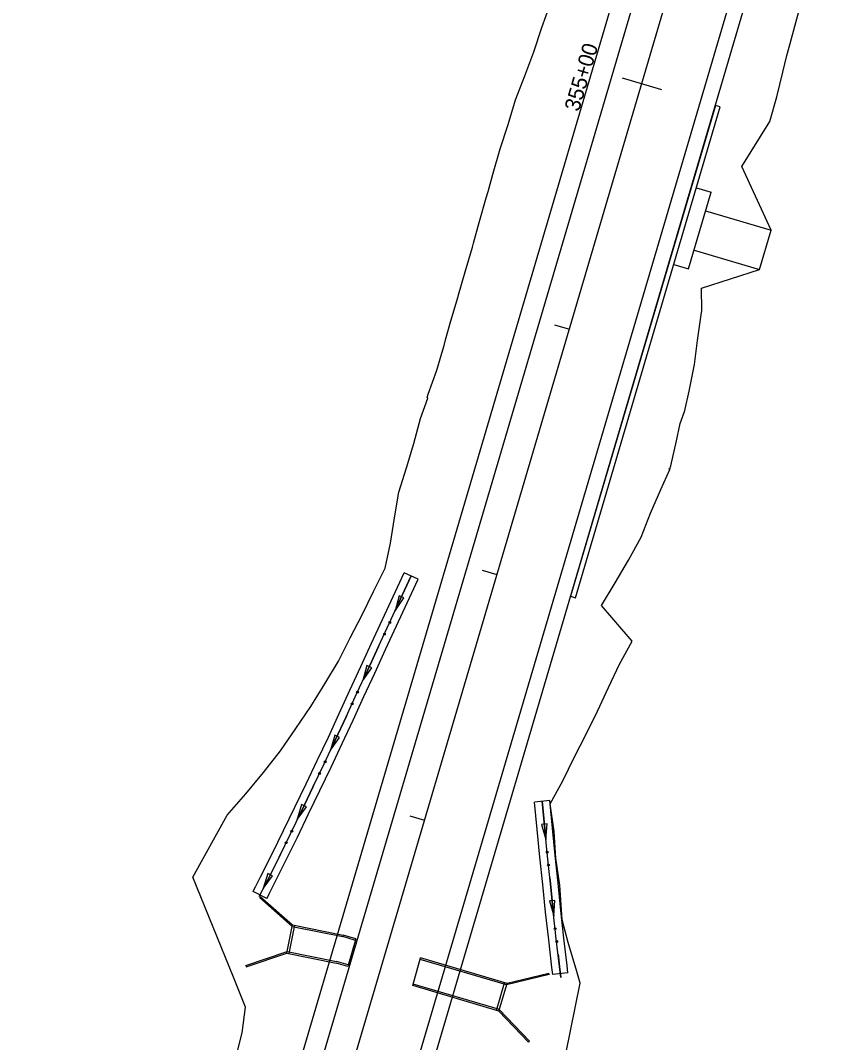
# Model space of a CAD drawing. Extents: x 948761 to 996004, y 1858548 to 1925175.
# Drawn here: x 961025.4 to 961348.3, y 1906157.3 to 1906556.8 of the extents above; entities that cross this region are included whole.
import ezdxf

# ---------------------------------------------------------------- set-up
doc = ezdxf.new("R2010")
doc.units = 0
for name, color, linetype in [('62', 7, 'Continuous'), ('R_Drainage', 7, 'Continuous'), ('R_Horz Alg', 7, 'Continuous'), ('R_Horz Alg Annot', 7, 'Continuous'), ('R_Proposed Const Limits', 7, 'Continuous'), ('R_Proposed Road', 7, 'Continuous')]:
    doc.layers.add(name, color=color, linetype=linetype)

msp = doc.modelspace()

# ---------------------------------------------------------------- linework, layer by layer
at = {"layer": '62'}
for p, q in [((961180.83, 1906338.42), (961175.38, 1906340.94)), ((961173.37, 1906331.95), (961171.81, 1906326.06)), ((961171.81, 1906326.06), (961175.29, 1906331.06)), ((961175.29, 1906331.06), (961173.37, 1906331.95)), ((961160.77, 1906304.68), (961159.22, 1906298.79)), ((961159.22, 1906298.79), (961162.69, 1906303.8)), ((961162.69, 1906303.8), (961160.77, 1906304.68)), ((961148.22, 1906277.4), (961146.61, 1906271.53)), ((961150.14, 1906276.49), (961148.22, 1906277.4)), ((961146.61, 1906271.53), (961150.14, 1906276.49)), ((961135.26, 1906250.31), (961133.61, 1906244.45)), ((961133.61, 1906244.45), (961137.16, 1906249.4)), ((961137.16, 1906249.4), (961135.26, 1906250.31)), ((961232.3, 1906251.88), (961226.33, 1906251.3)), ((961231.23, 1906242.74), (961229.13, 1906242.52)), ((961229.13, 1906242.52), (961230.79, 1906236.66)), ((961230.79, 1906236.66), (961231.23, 1906242.74)), ((961122.05, 1906223.35), (961120.31, 1906217.51)), ((961120.31, 1906217.51), (961123.94, 1906222.41)), ((961123.94, 1906222.41), (961122.05, 1906223.35)), ((961121.71, 1906213.61), (961116.34, 1906216.29)), ((961234.3, 1906212.86), (961232.2, 1906212.64)), ((961232.2, 1906212.64), (961233.86, 1906206.78)), ((961233.86, 1906206.78), (961234.3, 1906212.86)), ((961239.42, 1906184.56), (961233.46, 1906183.87))]:
    msp.add_line(p, q, dxfattribs=at)
for points in [[(961116.34, 1906216.29), (961117.32, 1906218.24), (961117.41, 1906218.43), (961119.23, 1906222.06), (961123.77, 1906231.13), (961128.24, 1906240.22), (961132.63, 1906249.33), (961137.03, 1906258.46), (961141.42, 1906267.59), (961145.75, 1906276.71), (961149.97, 1906285.87), (961154.19, 1906295.05), (961158.42, 1906304.23), (961162.65, 1906313.41), (961175.38, 1906340.94)], [(961118.73, 1906214.35), (961120, 1906216.89), (961120.09, 1906217.08), (961121.91, 1906220.71), (961126.46, 1906229.8), (961130.94, 1906238.9), (961135.33, 1906248.03), (961139.73, 1906257.16), (961144.12, 1906266.29), (961148.46, 1906275.44), (961152.69, 1906284.62), (961156.92, 1906293.8), (961161.15, 1906302.98), (961165.38, 1906312.15), (961169.62, 1906321.33), (961173.86, 1906330.5), (961178.1, 1906339.68)], [(961121.71, 1906213.61), (961122.68, 1906215.55), (961122.77, 1906215.74), (961124.59, 1906219.37), (961129.15, 1906228.47), (961133.63, 1906237.59), (961138.03, 1906246.73), (961142.43, 1906255.86), (961146.83, 1906265), (961151.18, 1906274.17), (961155.41, 1906283.36), (961159.64, 1906292.54), (961163.87, 1906301.72), (961168.1, 1906310.9), (961180.83, 1906338.42)], [(961178.1, 1906339.68), (961173.86, 1906330.5), (961171.81, 1906326.06)], [(961165.5, 1906312.41), (961165.38, 1906312.15), (961161.15, 1906302.98), (961159.22, 1906298.79)], [(961165.51, 1906312.45), (961165.5, 1906312.41)], [(961152.93, 1906285.13), (961152.69, 1906284.62), (961148.46, 1906275.44), (961146.61, 1906271.53)], [(961152.94, 1906285.17), (961152.93, 1906285.13)], [(961140.11, 1906257.96), (961139.73, 1906257.16), (961135.33, 1906248.03), (961133.61, 1906244.45)], [(961140.13, 1906258), (961140.11, 1906257.96)], [(961233.46, 1906183.87), (961233.13, 1906186.68), (961231.88, 1906197.49), (961230.69, 1906208.28), (961229.59, 1906219.04), (961228.48, 1906229.8), (961227.38, 1906240.55), (961226.33, 1906251.3)], [(961236.61, 1906182.71), (961236.11, 1906187.03), (961234.86, 1906197.82), (961233.67, 1906208.6), (961232.57, 1906219.35), (961231.47, 1906230.1), (961230.36, 1906240.85), (961229.32, 1906251.59)], [(961229.32, 1906251.59), (961230.36, 1906240.85), (961230.79, 1906236.66)], [(961239.42, 1906184.56), (961239.09, 1906187.37), (961237.84, 1906198.16), (961236.66, 1906208.92), (961235.56, 1906219.66), (961234.45, 1906230.41), (961233.35, 1906241.15), (961232.3, 1906251.88)], [(961127.02, 1906230.93), (961126.46, 1906229.8), (961121.91, 1906220.71), (961120.31, 1906217.51)], [(961127.03, 1906230.97), (961127.02, 1906230.93)], [(961232.33, 1906221.74), (961232.33, 1906221.7)], [(961232.33, 1906221.7), (961232.57, 1906219.35), (961233.67, 1906208.6), (961233.87, 1906206.78)], [(961235.55, 1906191.87), (961235.55, 1906191.84)], [(961235.55, 1906191.84), (961236.11, 1906187.03), (961236.61, 1906182.71)]]:
    msp.add_lwpolyline(points, dxfattribs=at)
for centre in [(961169.74, 1906321.5), (961167.64, 1906316.96), (961157.16, 1906294.23), (961155.06, 1906289.68), (961144.5, 1906266.99), (961142.33, 1906262.47), (961131.47, 1906239.92), (961129.26, 1906235.42), (961231.34, 1906231.68), (961231.85, 1906226.7), (961234.46, 1906201.81), (961235.01, 1906196.83)]:
    msp.add_circle(centre, 0.375, dxfattribs=at)
at = {"layer": 'R_Drainage'}
for p, q in [((961118.82, 1906214.03), (961131.66, 1906202.7)), ((961119.15, 1906214.41), (961131.7, 1906203.32)), ((961129.47, 1906192.3), (961131.7, 1906203.32)), ((961130.45, 1906192.1), (961132.68, 1906203.13)), ((961131.66, 1906202.7), (961151.36, 1906198.71)), ((961131.7, 1906203.32), (961151.51, 1906199.32)), ((961156.37, 1906197.24), (961151.36, 1906198.71)), ((961156.54, 1906197.84), (961151.51, 1906199.32)), ((961113.44, 1906187.44), (961129.68, 1906192.89)), ((961113.6, 1906186.96), (961129.47, 1906192.3)), ((961129.47, 1906192.3), (961148.8, 1906188.39)), ((961129.68, 1906192.89), (961148.95, 1906189)), ((961215.45, 1906179.81), (961181.62, 1906189.79)), ((961215.63, 1906180.41), (961181.79, 1906190.39)), ((961113.44, 1906187.44), (961113.6, 1906186.96)), ((961153.36, 1906187.04), (961148.8, 1906188.39)), ((961153.54, 1906187.64), (961148.95, 1906189)), ((961232.03, 1906183.85), (961215.37, 1906179.84)), ((961231.91, 1906184.34), (961215.63, 1906180.41)), ((961231.91, 1906184.34), (961232.03, 1906183.85)), ((961212.44, 1906169.62), (961178.73, 1906179.56)), ((961212.62, 1906170.22), (961178.9, 1906180.17)), ((961211.49, 1906169.9), (961214.67, 1906180.69)), ((961212.44, 1906169.62), (961215.63, 1906180.41)), ((961223.99, 1906157.48), (961212.44, 1906169.62)), ((961224.35, 1906157.83), (961212.54, 1906170.24)), ((961224.35, 1906157.83), (961223.99, 1906157.48))]:
    msp.add_line(p, q, dxfattribs=at)
for points in [[(961156.54, 1906197.84), (961153.36, 1906187.04)], [(961178.73, 1906179.56), (961181.79, 1906190.39)]]:
    msp.add_lwpolyline(points, dxfattribs=at)
at = {"layer": 'R_Horz Alg'}
msp.add_line((961044.57, 1905773.69), (961317.38, 1906698.54), dxfattribs=at)
at = {"layer": 'R_Horz Alg Annot'}
for points in [[(961260.59, 1906534.29), (961275.93, 1906529.77)], [(961234.21, 1906437.81), (961239.97, 1906436.11)], [(961205.92, 1906341.9), (961211.67, 1906340.2)], [(961177.63, 1906245.98), (961183.38, 1906244.29)]]:
    msp.add_lwpolyline(points, dxfattribs=at)
at = {"layer": 'R_Proposed Const Limits'}
for points in [[(961318.87, 1906474.81), (961307.38, 1906499.64), (961318.37, 1906517.25), (961321.02, 1906526.89), (961323.37, 1906536.62), (961325.03, 1906543.03), (961325.91, 1906546.3), (961328.5, 1906555.96), (961331.1, 1906565.62), (961331.62, 1906567.55), (961333.74, 1906575.27), (961335.67, 1906582), (961336.49, 1906584.89), (961339.24, 1906594.5), (961339.83, 1906596.41), (961342.19, 1906604.05), (961345.16, 1906613.6), (961348.32, 1906623.1)], [(961167.98, 1906342.66), (961170, 1906352.49), (961171.63, 1906362.44), (961173.34, 1906372.36), (961176.25, 1906381.93), (961179.18, 1906391.49), (961181.78, 1906401.15), (961184.65, 1906409.2), (961184.68, 1906409.26), (961184.68, 1906409.27), (961184.33, 1906409.37), (961184.83, 1906410.67), (961188.19, 1906420.11), (961190.14, 1906426.71), (961190.98, 1906429.71), (961191.58, 1906431.92), (961193.69, 1906439.34), (961196.52, 1906448.93), (961196.69, 1906449.52), (961199.2, 1906458.56), (961202.07, 1906468.14), (961202.54, 1906469.69), (961204.72, 1906477.79), (961207.46, 1906487.41), (961208.18, 1906489.92), (961210.17, 1906497.03), (961212.92, 1906506.65), (961216.02, 1906516.16), (961218.97, 1906525.72), (961222.52, 1906535.09), (961226.07, 1906544.47), (961229.16, 1906553.99), (961232.64, 1906563.39)], [(961232.44, 1906250.67), (961237.39, 1906259.63), (961241.86, 1906268.74), (961246.53, 1906277.79), (961251.02, 1906286.89), (961255.3, 1906296.05), (961259.57, 1906305.22), (961264.51, 1906314.19), (961252.57, 1906328.14), (961257.93, 1906336.98), (961263.08, 1906345.89), (961267.97, 1906354.87), (961271.71, 1906364.2), (961275.71, 1906373.44), (961279.2, 1906381.31), (961279.22, 1906381.37), (961278.82, 1906381.5), (961279.25, 1906381.37), (961279.69, 1906382.69), (961281.89, 1906392.47), (961283.32, 1906399.22), (961284.33, 1906402.18), (961285.07, 1906404.35), (961286.82, 1906411.87), (961288.77, 1906421.72), (961288.83, 1906422.34), (961290.1, 1906431.75), (961291.52, 1906441.76), (961291.75, 1906443.37), (961291.64, 1906452.15), (961314.34, 1906459.46)], [(961092.77, 1906221.89), (961106.24, 1906246.19), (961113.46, 1906254.49), (961120.34, 1906262.88), (961127.09, 1906271.31), (961133.04, 1906279.99), (961138.89, 1906288.69), (961144.34, 1906297.51), (961149.67, 1906306.36), (961154.26, 1906315.43), (961159.01, 1906324.46), (961163.44, 1906333.58), (961167.98, 1906342.66)], [(961238.56, 1906152.94), (961244.22, 1906180.47), (961242.85, 1906185.04), (961239.44, 1906196.47), (961237.18, 1906205.31), (961236.23, 1906218.81), (961234.68, 1906229.43), (961234.02, 1906239.77), (961232.44, 1906250.67)], [(961097.56, 1906102.79), (961099.09, 1906112.76), (961101.69, 1906122.42), (961104.43, 1906132.04), (961107.19, 1906141.65), (961109.61, 1906151.36), (961112.05, 1906161.07), (961113.31, 1906171.12), (961108.61, 1906182.93), (961092.77, 1906221.89)]]:
    msp.add_lwpolyline(points, dxfattribs=at)
at = {"layer": 'R_Proposed Road'}
for p, q in [((961025.38, 1905779.35), (961298.19, 1906704.2)), ((961033.06, 1905777.09), (961305.87, 1906701.94)), ((961067.59, 1905766.9), (961340.4, 1906691.75)), ((961073.34, 1905765.2), (961346.15, 1906690.06)), ((961286.54, 1906459.68), (961295.39, 1906489.71)), ((961289.64, 1906491.41), (961295.39, 1906489.71)), ((961293.23, 1906482.37), (961318.87, 1906474.81)), ((961314.34, 1906459.46), (961318.87, 1906474.81)), ((961288.7, 1906467.02), (961314.34, 1906459.46)), ((961280.78, 1906461.38), (961286.54, 1906459.68))]:
    msp.add_line(p, q, dxfattribs=at)
msp.add_lwpolyline([(961240.45, 1906331.71), (961242.37, 1906331.15), (961298.95, 1906522.97), (961297.03, 1906523.54)], close=True, dxfattribs=at)

# ---------------------------------------------------------------- texts
at = {"layer": 'R_Horz Alg Annot'}
msp.add_text('355+00', height=6, rotation=73.5652, dxfattribs=at).set_placement((961243.66, 1906520.87))

doc.saveas('drawing.dxf')
